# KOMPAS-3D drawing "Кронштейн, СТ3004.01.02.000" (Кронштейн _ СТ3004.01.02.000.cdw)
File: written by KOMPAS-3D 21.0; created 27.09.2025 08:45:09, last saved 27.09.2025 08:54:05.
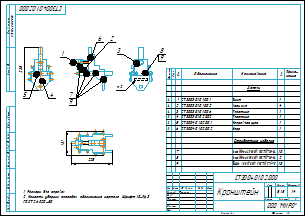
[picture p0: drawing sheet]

Sheet 1: A3, landscape

Document properties: Полное имя файла: C:\Users\Lutik\Yandex.Disk\Документы\Новая папка\Стапель №2\Стапель _ СТ3004.00.00.000\Опора _ СТ3004.01.00.000\2D\Кронштейн _ СТ3004.01.02.000\Кронштейн _ СТ3004.01.02.000.cdw; Масса: 5.184451

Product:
- Part/product: Кронштейн  | designation СТ3004.01.02.000
    Масса: 5.184451
  - Component [standard]: Винт М8-6gx35.56.019 ГОСТ 11738-84  | qty 2  | pos. 8  | Материал: Сталь 30 ГОСТ 1050-2013 (density 1000 kg/m3); Масса: 0.01831; Раздел спецификации: Стандартные изделия; Рассекать на разрезах: no
  - Component [standard]: Шайба A.8.01.10.019 ГОСТ 11371-78  | qty 10  | pos. 9  | Масса: 0.001828; Раздел спецификации: Стандартные изделия; Рассекать на разрезах: no
  - Component [standard]: Винт М8-6gx25.56.019 ГОСТ 11738-84  | qty 10  | pos. 7  | Материал: Сталь 30 ГОСТ 1050-2013 (density 1000 kg/m3); Масса: 0.01513; Раздел спецификации: Стандартные изделия; Рассекать на разрезах: no
  - Component [detail]: Косынка  | designation СТ3003.01.01.002  | qty 4  | pos. 2  | Материал: Лист$dБ-ПН-НО-6 ГОСТ 19903-2015;Ст3сп ГОСТ 14637-89$ (density 7850 kg/m3); Масса: 0.116828; Форматы листов документа: A4; source file: ..\..\..\..\Стапель _ СТ3003.00.00.000\Опора _ СТ3003.01.00.000\3D\Кронштейн _ СТ3003.01.01.000\Косынка _ СТ3003.01.01.002.m3d
  - Component [detail]: Пластина  | designation СТ3003.01.01.006  | pos. 3  | Материал: Лист$dБ-ПН-НО-16 ГОСТ 19903-2015;Ст3сп ГОСТ 14637-89$ (density 7850 kg/m3); Масса: 0.669577; Форматы листов документа: A4; source file: ..\..\..\..\Стапель _ СТ3003.00.00.000\Опора _ СТ3003.01.00.000\3D\Кронштейн _ СТ3003.01.01.000\Пластина _ СТ3003.01.01.006.m3d
  - Component [detail]: Винт  | designation СТ3003.01.01.001  | pos. 1  | Материал: Круг$d30 ГОСТ 2590-2006;Ст3сп ГОСТ 535-2005$ (density 7850 kg/m3); Масса: 0.311599; Форматы листов документа: A4; additional columns: 110; 6;Sortament:V6A25FA24F2024846A417965BB2EC510D;Material:VCD16F989E57D4831966FBA86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; source file: ..\..\..\..\Стапель _ СТ3003.00.00.000\Опора _ СТ3003.01.00.000\2D\Кронштейн _ СТ3003.01.01.000\Винт _ СТ3003.01.01.001.cdw, ..\..\..\..\Стапель _ СТ3003.00.00.000\Опора _ СТ3003.01.00.000\3D\Кронштейн _ СТ3003.01.01.000\Винт _ СТ3003.01.01.001.m3d
  - Component [detail]: Пластина  | designation СТ3003.01.02.002  | pos. 4  | Материал: Лист$dБ-ПН-НО-16 ГОСТ 19903-2015;Ст3сп ГОСТ 14637-89$ (density 7850 kg/m3); Масса: 0.780129; Форматы листов документа: A3; source file: ..\..\..\..\Стапель _ СТ3003.00.00.000\Опора _ СТ3003.01.00.000\3D\Кронштейн _ СТ3003.01.02.000\Пластина _ СТ3003.01.02.002.m3d
  - Component [detail]: Упор  | designation СТ3004.01.02.002  | pos. 6  | Материал: Сталь 45  ГОСТ 1050-2013 (density 7810 kg/m3); Масса: 1.036373; Форматы листов документа: A3; source file: ..\..\3D\Кронштейн _ СТ3004.01.02.000\Упор _ СТ3004.01.02.002.m3d, Упор _ СТ3004.01.02.002.cdw
  - Component [detail]: Направляющая  | designation СТ3004.01.02.001  | pos. 5  | Материал: Сталь 45  ГОСТ 1050-2013 (density 7810 kg/m3); Масса: 1.713262; Форматы листов документа: A3; source file: ..\..\3D\Кронштейн _ СТ3004.01.02.000\Направляющая _ СТ3004.01.02.001.m3d, Направляющая _ СТ3004.01.02.001.cdw

Title block, sheet 1: Наименование: Кронштейн; designation: СТ3004.01.02.000; Масса: 5,18; Количество листов документа: 1; organisation: ООО "МИРО"; Форматы листов документа: A3; Разработал: Тимонин

Views: Вид 1, Спереди
Referenced files in C:\Users\Lutik\Yandex.Disk\Документы\Новая папка\Стапель №2\Стапель _ СТ3004.00.00.000\Опора _ СТ3004.01.00.000\3D\Кронштейн _ СТ3004.01.02.000\: Кронштейн _ СТ3004.01.02.000.a3d, Направляющая _ СТ3004.01.02.001.m3d, Упор _ СТ3004.01.02.002.m3d
Referenced files in C:\Users\Lutik\Yandex.Disk\Документы\Новая папка\Стапель №2\Стапель _ СТ3004.00.00.000\Опора _ СТ3004.01.00.000\2D\Кронштейн _ СТ3004.01.02.000\: Направляющая _ СТ3004.01.02.001.cdw, Упор _ СТ3004.01.02.002.cdw
Referenced files in C:\Users\Lutik\Yandex.Disk\Документы\Новая папка\Стапель №2\Стапель _ СТ3003.00.00.000\Опора _ СТ3003.01.00.000\3D\Кронштейн _ СТ3003.01.02.000\: Пластина _ СТ3003.01.02.002.m3d
Referenced files in C:\Users\Lutik\Yandex.Disk\Документы\Новая папка\Стапель №2\Стапель _ СТ3003.00.00.000\Опора _ СТ3003.01.00.000\3D\Кронштейн _ СТ3003.01.01.000\: Косынка _ СТ3003.01.01.002.m3d, Винт _ СТ3003.01.01.001.m3d, Пластина _ СТ3003.01.01.006.m3d
Referenced files in C:\Users\Lutik\Yandex.Disk\Документы\Новая папка\Стапель №2\Стапель _ СТ3003.00.00.000\Опора _ СТ3003.01.00.000\2D\Кронштейн _ СТ3003.01.01.000\: Винт _ СТ3003.01.01.001.cdw
Referenced files in C:\Program Files\ASCON\KOMPAS-3D v21\Libs\PARTLib\DATA\vault\Methods\Kompas\3D\: PLib_Washer_1_712.m3d
Referenced files in C:\Program Files\ASCON\KOMPAS-3D v21\Libs\PartLib\DATA\VAULT\Methods\Kompas\3D\: PLib_Screw_GOST_11738_1500.m3d
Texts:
  Шайба A.8.01.10.019 ГОСТ 11371-78
  Крепежное изделие ГОСТ
  Шайба
  ГОСТ
  Винт М8-6gx25.56.019 ГОСТ 11738-84
  Винт
  СТ3004.01.02.001
  СТ3004.01.02.001
  Направляющая
  СТ3003.01.02.002
  Пластина
  СТ3003.01.01.002
  Косынка
  СТ3004.01.02.002
  СТ3004.01.02.002
  Упор
  Винт М8-6gx35.56.019 ГОСТ 11738-84
  СТ3003.01.01.001
  СТ3003.01.01.001
  СТ3003.01.01.006
  СТ3004.01.00.000
  СТ3004.01.02.001 Направляющая
  СТ3004.01.02.002 Упор
  СТ3003.01.02.002 Пластина
  СТ3003.01.01.002 Косынка
  СТ3003.01.01.001 Винт
  СТ3003.01.01.006 Пластина
  СТ3004.01.02.000 Кронштейн
Dimensions and other numbers on the sheet: 1; 2; 6; 7; 9; 01; 10; 019; 56; 40Х; 5; 4; 8; 3; 1:4; 5,18

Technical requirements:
  Размеры для справок.
  Нанести ударным способом обозначение чертежа. Шрифт 10-Пр3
